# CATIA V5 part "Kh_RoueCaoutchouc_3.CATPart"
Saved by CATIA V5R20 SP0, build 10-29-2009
Part number: Roue caoutchouc 3
Bounding box of the stored display mesh (mm): x -55.995 to 55.995, y -29 to 29, z -55.995 to 55.995
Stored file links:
  G:\Khaled_CFAO_2011\SIL\SIL_GR1\tmerino\Khaled\CAD_Thinkmotion\Kh_RoueCaoutchouc_3.CATPart
  G:\Khaled_CFAO_2011\SIL\SIL_GR1\tmerino\Khaled\CAD_Thinkmotion\Kh_Catalog.CATMaterial
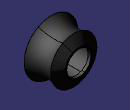
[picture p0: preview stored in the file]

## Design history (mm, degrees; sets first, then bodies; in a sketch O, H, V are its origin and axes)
Set1 "Plan"
  Plane1: type Offset, RefPlane zx-plane, Offset 0.619
  Sketch1 on Plane1, origin (0, 0.619, 0), H (-1, 0, 0), V (0, 0, 1)
    circle A1 centre (0, 0) radius 43.5676
Body1 (main body), material "Caoutchouc"
  Sketch2 on yz-plane, origin (0, 0, 0), H (0, 1, 0), V (0, 0, 1)
    line L1 (-29, -56) -> (-29, -42)
    point P3 (29, 90)
    line L2 (-29, -42) -> (-23, -42)
    line L3 (-23, -42) -> (-23, -34)
    line L4 (-23, -34) -> (23, -34)
    line L5 (23, -34) -> (23, -25)
    line L6 (23, -25) -> (29, -25)
    line L7 (29, -25) -> (29, -56)
    arc A1 centre (0, -83.55) radius 40 from (29, -56) to (-29, -56) ccw
    distance V L1 = 29
    length L1 = 14
    length L2 = 6
    length L3 = 8
    length L4 = 46
    length L5 = 9
    length L6 = 6
    vertical: L1 V, L3 V, L5 V, L7 V
    horizontal: L2 H, L4 H, L6 H
    fix: A1
  Shaft1: profile Sketch2, axis Sketch2.H, angle 360
  Sketch3 on face of Shaft1 from Sketch2.L3, origin (11.6205, -23, -36.2849), H (1, 0, 0), V (0, 0, 1)
    point P1 (26.3795, 36.2849)
    reference intersected line E1 through (0, 36.2849) direction (-1, 0) from xy-plane
    reference intersected line E2 through (-11.6205, 0) direction (0, 1) from yz-plane
    distance E1 P1 = 0
    distance E2 P1 = 38
  Hole1: placed by Sketch3, at (38, -23, 0) direction (0, 1, 0), diameter 3.5, depth 10, threaded, thread diameter 4, thread depth 10, pitch 1
  CircPattern1: of Hole1, instances 9, angular step 40, axis from face of Shaft1 from Sketch2.L4
  Chamfer1: length 12, angle 89, on edge [face of Shaft1 from Sketch2.A1 | face of Shaft1 from Sketch2.L7]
